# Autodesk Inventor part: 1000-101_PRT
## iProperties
Created: 2006-10
Part Number: 1000-101_PRT
Document SubType Name: Modeling
Designer: Andy Moles
Density: 7.85 g/cm^3
Material: Steel
Mass: 34.1276 g
Surface Area: 33.1583 cm^2
Volume: 4.34747 cm^3
Author: Andy Moles
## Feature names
1. Base1
